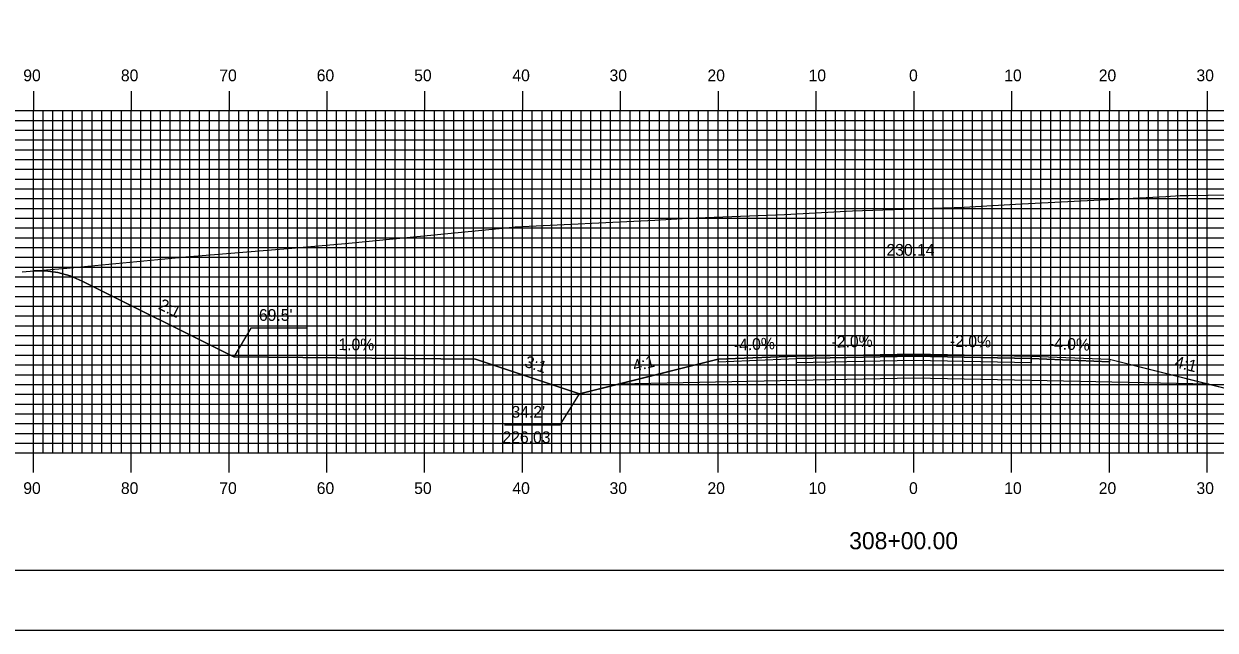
# Model space of a CAD drawing. Extents: x 1817670 to 1818013, y 442591 to 442811.
# Drawn here: x 1817744.6 to 1817866.4, y 442590.5 to 442652.5 of the extents above; entities that cross this region are included whole.
import ezdxf

# ---------------------------------------------------------------- set-up
doc = ezdxf.new("R2010")
doc.units = 0
for name, color, linetype in [('ANNOTATION', 7, 'Continuous'), ('BORDER', 7, 'Continuous'), ('D_Roadway_Centerline', 7, 'Continuous'), ('D_Roadway_Centerline_Text', 7, 'Continuous'), ('D_Roadway_Edge_Shoulder', 7, 'Continuous'), ('D_Roadway_Edge_TW', 7, 'Continuous'), ('D_Roadway_Pavement', 7, 'Continuous'), ('D_Roadway_SlopeLines', 7, 'Continuous'), ('D_Roadway_SubGrade', 7, 'Continuous'), ('H_V ANNOTATION', 7, 'Continuous'), ('MAJOR', 7, 'Continuous'), ('MINOR', 7, 'Continuous'), ('PLOT BOUNDARY', 7, 'Continuous'), ('S_Roadway_Centerline', 7, 'Continuous')]:
    doc.layers.add(name, color=color, linetype=linetype)

msp = doc.modelspace()

# ---------------------------------------------------------------- linework, layer by layer
at = {"layer": 'ANNOTATION'}
for points in [[(1817773.53, 442621.44), (1817767.84, 442621.44), (1817766.12, 442618.49)], [(1817793.76, 442611.54), (1817799.45, 442611.54), (1817801.44, 442614.7)]]:
    msp.add_lwpolyline(points, dxfattribs=at)
at = {"layer": 'BORDER'}
msp.add_lwpolyline([(1817686.01, 442596.67), (1818006.01, 442596.67), (1818006.01, 442806.67), (1817686.01, 442806.67)], close=True, dxfattribs=at)
at = {"layer": 'D_Roadway_Centerline'}
msp.add_lwpolyline([(1817745.61, 442627.29), (1817746.86, 442627.3), (1817748.11, 442627.13), (1817749.36, 442626.77), (1817750.61, 442626.24), (1817766.12, 442618.49), (1817790.81, 442618.24), (1817801.44, 442614.7), (1817805.44, 442615.7), (1817815.61, 442618.24), (1817823.61, 442618.56), (1817835.61, 442618.8), (1817847.61, 442618.56), (1817855.61, 442618.24), (1817865.79, 442615.7), (1817869.79, 442614.7), (1817880.42, 442618.24), (1817888.49, 442618.32), (1817920.61, 442634.38), (1817921.86, 442634.93), (1817923.11, 442635.33), (1817924.36, 442635.58), (1817925.61, 442635.67)], dxfattribs=at)
at = {"layer": 'D_Roadway_Edge_Shoulder'}
for points in [[(1817823.61, 442618.56), (1817815.61, 442618.24), (1817815.61, 442617.99), (1817823.61, 442618.31)], [(1817847.61, 442618.56), (1817855.61, 442618.24), (1817855.61, 442617.99), (1817847.61, 442618.31)]]:
    msp.add_lwpolyline(points, close=True, dxfattribs=at)
at = {"layer": 'D_Roadway_Edge_TW'}
msp.add_lwpolyline([(1817823.61, 442618.31), (1817823.61, 442618.56), (1817835.61, 442618.8), (1817847.61, 442618.56), (1817847.61, 442618.31), (1817835.61, 442618.55)], close=True, dxfattribs=at)
at = {"layer": 'D_Roadway_Pavement'}
msp.add_lwpolyline([(1817823.61, 442617.89), (1817823.61, 442618.31), (1817835.61, 442618.55), (1817847.61, 442618.31), (1817847.61, 442617.89), (1817835.61, 442618.13)], close=True, dxfattribs=at)
at = {"layer": 'D_Roadway_SlopeLines'}
for points in [[(1817790.81, 442618.24), (1817766.12, 442618.49), (1817750.61, 442626.24), (1817749.36, 442626.77), (1817748.11, 442627.13), (1817746.86, 442627.3), (1817745.61, 442627.29)], [(1817801.44, 442614.7), (1817790.81, 442618.24)], [(1817815.61, 442618.24), (1817801.44, 442614.7)], [(1817855.61, 442618.24), (1817869.79, 442614.7)]]:
    msp.add_lwpolyline(points, dxfattribs=at)
at = {"layer": 'D_Roadway_SubGrade'}
msp.add_lwpolyline([(1817823.61, 442616.06), (1817805.44, 442615.7), (1817815.61, 442618.24), (1817815.61, 442617.99), (1817823.61, 442618.31), (1817835.61, 442618.55), (1817847.61, 442618.31), (1817855.61, 442617.99), (1817855.61, 442618.24), (1817865.79, 442615.7), (1817847.61, 442616.06), (1817835.61, 442616.3)], close=True, dxfattribs=at)
at = {"layer": 'MAJOR'}
for p, q in [((1817745.61, 442645.67), (1817745.61, 442643.67)), ((1817755.61, 442645.67), (1817755.61, 442643.67)), ((1817765.61, 442645.67), (1817765.61, 442643.67)), ((1817775.61, 442645.67), (1817775.61, 442643.67)), ((1817785.61, 442645.67), (1817785.61, 442643.67)), ((1817795.61, 442645.67), (1817795.61, 442643.67)), ((1817805.61, 442645.67), (1817805.61, 442643.67)), ((1817815.61, 442645.67), (1817815.61, 442643.67)), ((1817825.61, 442645.67), (1817825.61, 442643.67)), ((1817835.61, 442645.67), (1817835.61, 442643.67)), ((1817845.61, 442645.67), (1817845.61, 442643.67)), ((1817855.61, 442645.67), (1817855.61, 442643.67)), ((1817865.61, 442645.67), (1817865.61, 442643.67)), ((1817695.61, 442643.67), (1817975.61, 442643.67)), ((1817695.61, 442643.67), (1817975.61, 442643.67)), ((1817745.61, 442608.67), (1817745.61, 442643.67)), ((1817755.61, 442608.67), (1817755.61, 442643.67)), ((1817765.61, 442608.67), (1817765.61, 442643.67)), ((1817775.61, 442608.67), (1817775.61, 442643.67)), ((1817785.61, 442608.67), (1817785.61, 442643.67)), ((1817795.61, 442608.67), (1817795.61, 442643.67)), ((1817805.61, 442608.67), (1817805.61, 442643.67)), ((1817815.61, 442608.67), (1817815.61, 442643.67)), ((1817825.61, 442608.67), (1817825.61, 442643.67)), ((1817835.61, 442608.67), (1817835.61, 442643.67)), ((1817845.61, 442608.67), (1817845.61, 442643.67)), ((1817855.61, 442608.67), (1817855.61, 442643.67)), ((1817865.61, 442608.67), (1817865.61, 442643.67)), ((1817695.61, 442638.67), (1817975.61, 442638.67)), ((1817695.61, 442633.67), (1817975.61, 442633.67)), ((1817695.61, 442628.67), (1817975.61, 442628.67)), ((1817695.61, 442623.67), (1817975.61, 442623.67)), ((1817695.61, 442618.67), (1817975.61, 442618.67)), ((1817695.61, 442613.67), (1817975.61, 442613.67)), ((1817695.61, 442608.67), (1817975.61, 442608.67)), ((1817695.61, 442608.67), (1817975.61, 442608.67)), ((1817745.61, 442606.66), (1817745.61, 442608.67)), ((1817755.61, 442606.66), (1817755.61, 442608.67)), ((1817765.61, 442606.66), (1817765.61, 442608.67)), ((1817775.61, 442606.66), (1817775.61, 442608.67)), ((1817785.61, 442606.66), (1817785.61, 442608.67)), ((1817795.61, 442606.66), (1817795.61, 442608.67)), ((1817805.61, 442606.66), (1817805.61, 442608.67)), ((1817815.61, 442606.66), (1817815.61, 442608.67)), ((1817825.61, 442606.66), (1817825.61, 442608.67)), ((1817835.61, 442606.66), (1817835.61, 442608.67)), ((1817845.61, 442606.66), (1817845.61, 442608.67)), ((1817855.61, 442606.66), (1817855.61, 442608.67)), ((1817865.61, 442606.66), (1817865.61, 442608.67))]:
    msp.add_line(p, q, dxfattribs=at)
at = {"layer": 'MINOR'}
for p, q in [((1817746.61, 442608.67), (1817746.61, 442643.67)), ((1817747.61, 442608.67), (1817747.61, 442643.67)), ((1817748.61, 442608.67), (1817748.61, 442643.67)), ((1817749.61, 442608.67), (1817749.61, 442643.67)), ((1817750.61, 442608.67), (1817750.61, 442643.67)), ((1817751.61, 442608.67), (1817751.61, 442643.67)), ((1817752.61, 442608.67), (1817752.61, 442643.67)), ((1817753.61, 442608.67), (1817753.61, 442643.67)), ((1817754.61, 442608.67), (1817754.61, 442643.67)), ((1817756.61, 442608.67), (1817756.61, 442643.67)), ((1817757.61, 442608.67), (1817757.61, 442643.67)), ((1817758.61, 442608.67), (1817758.61, 442643.67)), ((1817759.61, 442608.67), (1817759.61, 442643.67)), ((1817760.61, 442608.67), (1817760.61, 442643.67)), ((1817761.61, 442608.67), (1817761.61, 442643.67)), ((1817762.61, 442608.67), (1817762.61, 442643.67)), ((1817763.61, 442608.67), (1817763.61, 442643.67)), ((1817764.61, 442608.67), (1817764.61, 442643.67)), ((1817766.61, 442608.67), (1817766.61, 442643.67)), ((1817767.61, 442608.67), (1817767.61, 442643.67)), ((1817768.61, 442608.67), (1817768.61, 442643.67)), ((1817769.61, 442608.67), (1817769.61, 442643.67)), ((1817770.61, 442608.67), (1817770.61, 442643.67)), ((1817771.61, 442608.67), (1817771.61, 442643.67)), ((1817772.61, 442608.67), (1817772.61, 442643.67)), ((1817773.61, 442608.67), (1817773.61, 442643.67)), ((1817774.61, 442608.67), (1817774.61, 442643.67)), ((1817776.61, 442608.67), (1817776.61, 442643.67)), ((1817777.61, 442608.67), (1817777.61, 442643.67)), ((1817778.61, 442608.67), (1817778.61, 442643.67)), ((1817779.61, 442608.67), (1817779.61, 442643.67)), ((1817780.61, 442608.67), (1817780.61, 442643.67)), ((1817781.61, 442608.67), (1817781.61, 442643.67)), ((1817782.61, 442608.67), (1817782.61, 442643.67)), ((1817783.61, 442608.67), (1817783.61, 442643.67)), ((1817784.61, 442608.67), (1817784.61, 442643.67)), ((1817786.61, 442608.67), (1817786.61, 442643.67)), ((1817787.61, 442608.67), (1817787.61, 442643.67)), ((1817788.61, 442608.67), (1817788.61, 442643.67)), ((1817789.61, 442608.67), (1817789.61, 442643.67)), ((1817790.61, 442608.67), (1817790.61, 442643.67)), ((1817791.61, 442608.67), (1817791.61, 442643.67)), ((1817792.61, 442608.67), (1817792.61, 442643.67)), ((1817793.61, 442608.67), (1817793.61, 442643.67)), ((1817794.61, 442608.67), (1817794.61, 442643.67)), ((1817796.61, 442608.67), (1817796.61, 442643.67)), ((1817797.61, 442608.67), (1817797.61, 442643.67)), ((1817798.61, 442608.67), (1817798.61, 442643.67)), ((1817799.61, 442608.67), (1817799.61, 442643.67)), ((1817800.61, 442608.67), (1817800.61, 442643.67)), ((1817801.61, 442608.67), (1817801.61, 442643.67)), ((1817802.61, 442608.67), (1817802.61, 442643.67)), ((1817803.61, 442608.67), (1817803.61, 442643.67)), ((1817804.61, 442608.67), (1817804.61, 442643.67)), ((1817806.61, 442608.67), (1817806.61, 442643.67)), ((1817807.61, 442608.67), (1817807.61, 442643.67)), ((1817808.61, 442608.67), (1817808.61, 442643.67)), ((1817809.61, 442608.67), (1817809.61, 442643.67)), ((1817810.61, 442608.67), (1817810.61, 442643.67)), ((1817811.61, 442608.67), (1817811.61, 442643.67)), ((1817812.61, 442608.67), (1817812.61, 442643.67)), ((1817813.61, 442608.67), (1817813.61, 442643.67)), ((1817814.61, 442608.67), (1817814.61, 442643.67)), ((1817816.61, 442608.67), (1817816.61, 442643.67)), ((1817817.61, 442608.67), (1817817.61, 442643.67)), ((1817818.61, 442608.67), (1817818.61, 442643.67)), ((1817819.61, 442608.67), (1817819.61, 442643.67)), ((1817820.61, 442608.67), (1817820.61, 442643.67)), ((1817821.61, 442608.67), (1817821.61, 442643.67)), ((1817822.61, 442608.67), (1817822.61, 442643.67)), ((1817823.61, 442608.67), (1817823.61, 442643.67)), ((1817824.61, 442608.67), (1817824.61, 442643.67)), ((1817826.61, 442608.67), (1817826.61, 442643.67)), ((1817827.61, 442608.67), (1817827.61, 442643.67)), ((1817828.61, 442608.67), (1817828.61, 442643.67)), ((1817829.61, 442608.67), (1817829.61, 442643.67)), ((1817830.61, 442608.67), (1817830.61, 442643.67)), ((1817831.61, 442608.67), (1817831.61, 442643.67)), ((1817832.61, 442608.67), (1817832.61, 442643.67)), ((1817833.61, 442608.67), (1817833.61, 442643.67)), ((1817834.61, 442608.67), (1817834.61, 442643.67)), ((1817836.61, 442608.67), (1817836.61, 442643.67)), ((1817837.61, 442608.67), (1817837.61, 442643.67)), ((1817838.61, 442608.67), (1817838.61, 442643.67)), ((1817839.61, 442608.67), (1817839.61, 442643.67)), ((1817840.61, 442608.67), (1817840.61, 442643.67)), ((1817841.61, 442608.67), (1817841.61, 442643.67)), ((1817842.61, 442608.67), (1817842.61, 442643.67)), ((1817843.61, 442608.67), (1817843.61, 442643.67)), ((1817844.61, 442608.67), (1817844.61, 442643.67)), ((1817846.61, 442608.67), (1817846.61, 442643.67)), ((1817847.61, 442608.67), (1817847.61, 442643.67)), ((1817848.61, 442608.67), (1817848.61, 442643.67)), ((1817849.61, 442608.67), (1817849.61, 442643.67)), ((1817850.61, 442608.67), (1817850.61, 442643.67)), ((1817851.61, 442608.67), (1817851.61, 442643.67)), ((1817852.61, 442608.67), (1817852.61, 442643.67)), ((1817853.61, 442608.67), (1817853.61, 442643.67)), ((1817854.61, 442608.67), (1817854.61, 442643.67)), ((1817856.61, 442608.67), (1817856.61, 442643.67)), ((1817857.61, 442608.67), (1817857.61, 442643.67)), ((1817858.61, 442608.67), (1817858.61, 442643.67)), ((1817859.61, 442608.67), (1817859.61, 442643.67)), ((1817860.61, 442608.67), (1817860.61, 442643.67)), ((1817861.61, 442608.67), (1817861.61, 442643.67)), ((1817862.61, 442608.67), (1817862.61, 442643.67)), ((1817863.61, 442608.67), (1817863.61, 442643.67)), ((1817864.61, 442608.67), (1817864.61, 442643.67)), ((1817695.61, 442642.67), (1817975.61, 442642.67)), ((1817695.61, 442641.67), (1817975.61, 442641.67)), ((1817695.61, 442640.67), (1817975.61, 442640.67)), ((1817695.61, 442639.67), (1817975.61, 442639.67)), ((1817695.61, 442637.67), (1817975.61, 442637.67)), ((1817695.61, 442636.67), (1817975.61, 442636.67)), ((1817695.61, 442635.67), (1817975.61, 442635.67)), ((1817695.61, 442634.67), (1817975.61, 442634.67)), ((1817695.61, 442632.67), (1817975.61, 442632.67)), ((1817695.61, 442631.67), (1817975.61, 442631.67)), ((1817695.61, 442630.67), (1817975.61, 442630.67)), ((1817695.61, 442629.67), (1817975.61, 442629.67)), ((1817695.61, 442627.67), (1817975.61, 442627.67)), ((1817695.61, 442626.67), (1817975.61, 442626.67)), ((1817695.61, 442625.67), (1817975.61, 442625.67)), ((1817695.61, 442624.67), (1817975.61, 442624.67)), ((1817695.61, 442622.67), (1817975.61, 442622.67)), ((1817695.61, 442621.67), (1817975.61, 442621.67)), ((1817695.61, 442620.67), (1817975.61, 442620.67)), ((1817695.61, 442619.67), (1817975.61, 442619.67)), ((1817695.61, 442617.67), (1817975.61, 442617.67)), ((1817695.61, 442616.67), (1817975.61, 442616.67)), ((1817695.61, 442615.67), (1817975.61, 442615.67)), ((1817695.61, 442614.67), (1817975.61, 442614.67)), ((1817695.61, 442612.67), (1817975.61, 442612.67)), ((1817695.61, 442611.67), (1817975.61, 442611.67)), ((1817695.61, 442610.67), (1817975.61, 442610.67)), ((1817695.61, 442609.67), (1817975.61, 442609.67))]:
    msp.add_line(p, q, dxfattribs=at)
at = {"layer": 'PLOT BOUNDARY'}
msp.add_lwpolyline([(1817669.83, 442590.55), (1818009.83, 442590.55), (1818009.83, 442810.55), (1817669.83, 442810.55)], close=True, dxfattribs=at)
at = {"layer": 'S_Roadway_Centerline'}
msp.add_lwpolyline([(1817744.46, 442627.2), (1817749.03, 442627.56), (1817761.2, 442628.71), (1817772.02, 442629.62), (1817777.49, 442630.08), (1817793.57, 442631.66), (1817794.58, 442631.76), (1817794.85, 442631.78), (1817809.15, 442632.47), (1817812.5, 442632.68), (1817822.39, 442633.05), (1817829.36, 442633.42), (1817840.76, 442633.8), (1817846, 442634.11), (1817861.37, 442634.89), (1817862.83, 442634.98), (1817863.12, 442634.99), (1817863.69, 442634.99), (1817889.78, 442635.42)], dxfattribs=at)

# ---------------------------------------------------------------- texts
at = {"layer": 'ANNOTATION'}
for s, rotation, p in [('2:1', 333.4349, (1817758.3, 442623.43)), ('1.0%', 359.4271, (1817776.79, 442619.18)), ('-4.0%', 2.2906, (1817817.24, 442619.11)), ('-2.0%', 1.1458, (1817827.22, 442619.43)), ('-2.0%', 358.8542, (1817839.3, 442619.53)), ('-4.0%', 357.7094, (1817849.4, 442619.29)), ('3:1', 341.5651, (1817795.73, 442617.51)), ('4:1', 14.0362, (1817807.06, 442616.97)), ('4:1', 345.9638, (1817862.21, 442617.45))]:
    msp.add_text(s, height=1.2, rotation=rotation, dxfattribs=at).set_placement(p)
for s, p in [("69.5'", (1817768.67, 442622.17)), ("34.2'", (1817794.49, 442612.27)), ('226.03', (1817793.57, 442609.67))]:
    msp.add_text(s, height=1.2, dxfattribs=at).set_placement(p)
at = {"layer": 'D_Roadway_Centerline'}
for s, p in [('C', (1817835.61, 442618.8)), ('L', (1817835.61, 442618.79))]:
    msp.add_text(s, height=0.0146, dxfattribs=at).set_placement(p)
at = {"layer": 'D_Roadway_Centerline_Text'}
msp.add_text('230.14', height=1.2, dxfattribs=at).set_placement((1817832.82, 442628.83))
at = {"layer": 'H_V ANNOTATION'}
for s, height, p in [('90', 1.2, (1817744.58, 442646.67)), ('80', 1.2, (1817754.56, 442646.67)), ('70', 1.2, (1817764.62, 442646.67)), ('60', 1.2, (1817774.58, 442646.67)), ('50', 1.2, (1817784.54, 442646.67)), ('40', 1.2, (1817794.58, 442646.67)), ('30', 1.2, (1817804.51, 442646.67)), ('20', 1.2, (1817814.52, 442646.67)), ('10', 1.2, (1817824.86, 442646.67)), ('0', 1.2, (1817835.13, 442646.67)), ('10', 1.2, (1817844.86, 442646.67)), ('20', 1.2, (1817854.52, 442646.67)), ('30', 1.2, (1817864.51, 442646.67)), ('90', 1.2, (1817744.58, 442604.47)), ('80', 1.2, (1817754.56, 442604.47)), ('70', 1.2, (1817764.62, 442604.47)), ('60', 1.2, (1817774.58, 442604.47)), ('50', 1.2, (1817784.54, 442604.47)), ('40', 1.2, (1817794.58, 442604.47)), ('30', 1.2, (1817804.51, 442604.47)), ('20', 1.2, (1817814.52, 442604.47)), ('10', 1.2, (1817824.86, 442604.47)), ('0', 1.2, (1817835.13, 442604.47)), ('10', 1.2, (1817844.86, 442604.47)), ('20', 1.2, (1817854.52, 442604.47)), ('30', 1.2, (1817864.51, 442604.47)), ('308+00.00', 1.75, (1817829.01, 442598.82))]:
    msp.add_text(s, height=height, dxfattribs=at).set_placement(p)

doc.saveas('drawing.dxf')
